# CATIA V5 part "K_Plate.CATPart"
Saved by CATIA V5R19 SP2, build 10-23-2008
Part number: Plate
Bounding box of the stored display mesh (mm): x -52.355 to 52.355, y -25 to 25, z -12 to 41.999
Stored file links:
  G:\Khaled_CFAO_2011\ST2M\ST2M_GR1\bgaltie\bgaltie\Khaled\CAD_thinkMOTION\K_Plate.CATPart
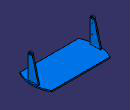
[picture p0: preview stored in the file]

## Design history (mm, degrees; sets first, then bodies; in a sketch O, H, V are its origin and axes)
AxisSystem1: origin (0, 0, 0), X (1, 0, 0), Y (0, 1, 0), Z (0, 0, 1)
Body1 (main body)
  Sketch1 on XY plane of AxisSystem1, origin (0, 0, 0), H (1, 0, 0), V (0, 1, 0)
    arc A1 centre (0, 0) radius 52.3546 from (46, -25) to (46, 25) ccw
    point P1 (0, 0)
    line L1 (-46, 25) -> (46, 25)
    line L2 (46, -25) -> (-46, -25)
    arc A2 centre (0, 0) radius 52.3546 from (-46, 25) to (-46, -25) ccw
    length L2 = 92
    distance L1 L2 = 50
    coincidence: P1 O, A1 A2
    horizontal: L1 H, L2 H
    symmetry: L2 L1 H
  Pad1: profile Sketch1, direction (0, 0, 1), length 2
  Sketch2 on face of Pad1, origin (0, 0, 0), H (1, 0, 0), V (0, -1, 0)
    circle A1 centre (0, 0) radius 7.5
    point P1 (0, 0)
    radius A1 = 7.5
    coincidence: P1 O
  Pad2: profile Sketch2, direction (0, 0, -1), length 12
  Sketch3 on end face of Pad1, origin (0, 0, 2), H (1, 0, 0), V (0, 1, 0)
    line L1 (-50, 8) -> (-48, 8)
    line L2 (-48, 8) -> (-48, -8)
    line L3 (-48, -8) -> (-50, -8)
    line L4 (-50, -8) -> (-50, 8)
    reference projected line E1 through (0, 0) direction (0, 1) from edge [YZ plane of AxisSystem1 | XY plane of AxisSystem1]
    reference projected line E2 through (0, 0) direction (1, 0) from edge [XY plane of AxisSystem1 | ZX plane of AxisSystem1]
    distance L2 E1 = 48
    length L3 = 2
    distance L3 L1 = 16
    horizontal: L1 H, L3 H
    vertical: L2 V, L4 V
    symmetry: L3 L1 E2
  Pad3: profile Sketch3, direction (0, 0, 1), length 40
  Sketch4 on face of Pad3 from Sketch3.L4, origin (-50, 0, 0), H (0, -1, 0), V (0, 0, 1)
    arc A1 centre (5, 39) radius 3 from (8, 39) to (2.1018, 39.775) ccw
    reference projected line E1 (8, 2) -> (8, 42) from edge [face of Pad3 from Sketch3.L3 | face of Pad3 from Sketch3.L4]
    reference projected line E2 (-8, 42) -> (8, 42) from edge [face of Pad3 from Sketch3.L4 | end face of Pad3]
    line L1 (-8, 2) -> (2.1018, 39.775)
    point P2 (-8, 2)
    reference projected point E3 (-8, 2) from vertex [face of Pad3 from Sketch3.L1 | end face of Pad1 | face of Pad3 from Sketch3.L4]
    line L2 (8, 39) -> (8, 48.3179)
    line L3 (8, 48.3179) -> (-8, 48.3179)
    line L4 (-8, 48.3179) -> (-8, 2)
    point P7 (-8, 2)
    radius A1 = 3
    tangency: A1 E1, E2 A1, L1 A1, L2 A1
    coincidence: P2 E3, P7 L1, P2 P7
    vertical: L2 V, L4 V
    perpendicularity: L3 L2
  Pocket1: profile Sketch4, direction (1, 0, 0), through (limit type 6)
  Sketch5 on face of Pad3 from Sketch3.L4, origin (-50, -3.6294, 35.6473), H (0, 1, 0), V (0, 0, -1)
    point P1 (-1.3706, -3.3527)
    reference projected arc E1 centre (-1.3706, -3.3527) radius 3 from (-4.3706, -3.3527) to (1.5275, -4.1277) ccw from edge [face of Pad3 from Sketch3.L4 | face of Pocket1]
    concentricity: P1 E1
  Hole1: placed by Sketch5, at (-50, -5, 39) direction (1, 0, 0), diameter 4, through (limit type 6)
  Sketch6 on face of Pad3 from Sketch3.L2, origin (-48, -3.8296, 24.6501), H (0, 1, 0), V (0, 0, 1)
    point P1 (-1.1704, 7.3499)
    reference projected line E2 (-4.1704, -22.6501) -> (-4.1704, 17.3499) from edge [face of Pad3 from Sketch3.L2 | face of Pad3 from Sketch3.L3]
    reference projected line E3 (-21.1704, -22.6501) -> (28.8296, -22.6501) from edge [face of Pad1 from Sketch1.A1 | end face of Pad1]
    distance P1 E2 = 3
    distance P1 E3 = 30
  Hole2: placed by Sketch6, at (-48, -5, 32) direction (-1, 0, 0), diameter 1, depth 1
  Sketch7 on face of Pad3 from Sketch3.L2, origin (-48, -2.9576, 16.6162), H (0, 1, 0), V (0, 0, 1)
    point P1 (-2.0424, 0.3838)
    reference projected line E1 (-5.0424, -14.6162) -> (-5.0424, 25.3838) from edge [face of Pad3 from Sketch3.L2 | face of Pad3 from Sketch3.L3]
    reference projected line E2 (-22.0424, -14.6162) -> (27.9576, -14.6162) from edge [face of Pad1 from Sketch1.A1 | end face of Pad1]
    distance P1 E1 = 3
    distance P1 E2 = 15
  Hole3: placed by Sketch7, at (-48, -5, 17) direction (-1, 0, 0), diameter 1, depth 1
  Mirror1: of Pad3, Sketch3, Pocket1, Sketch4, Hole1, Hole2, Hole3, about YZ plane of AxisSystem1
